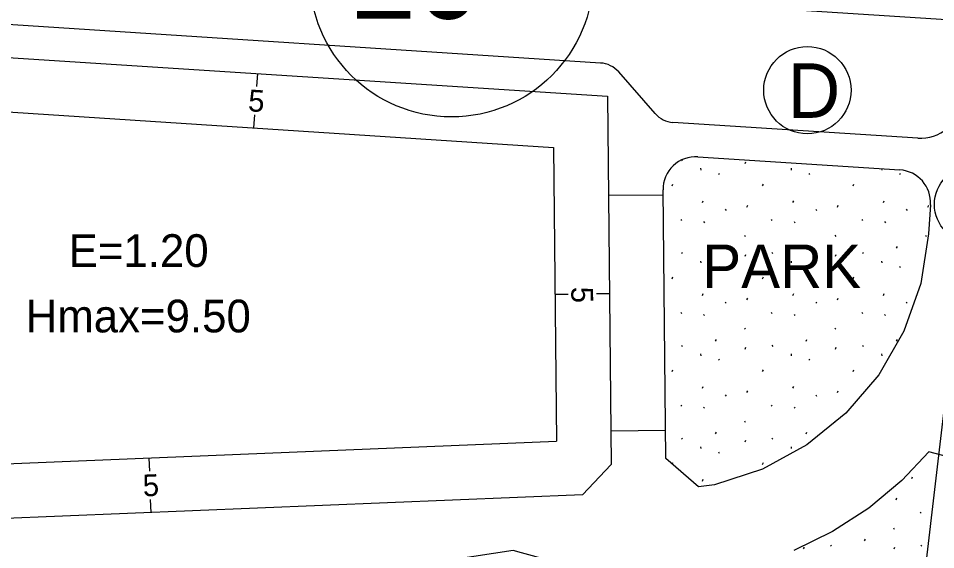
# Model space of a CAD drawing. Extents: x 419396 to 421519, y 4453567 to 4456767.
# Drawn here: x 421028 to 421112.1, y 4454579.1 to 4454627.8 of the extents above; entities that cross this region are included whole.
import ezdxf

# ---------------------------------------------------------------- set-up
doc = ezdxf.new("R2010")
doc.units = 0
for name, color, linetype in [('0_KADASTRO', 7, 'Continuous'), ('Level 20', 7, 'Continuous'), ('Level 28', 7, 'Continuous'), ('Level 29', 7, 'Continuous'), ('Level 30', 7, 'Continuous'), ('Level 41', 7, 'Continuous'), ('Level 55', 7, 'Continuous'), ('Level 58', 7, 'Continuous'), ('Level 61', 7, 'Continuous'), ('Level 62', 7, 'Continuous')]:
    doc.layers.add(name, color=color, linetype=linetype)

msp = doc.modelspace()

# ---------------------------------------------------------------- linework, layer by layer
at = {"layer": '0_KADASTRO'}
msp.add_lwpolyline([(421115.84, 4454617.61), (421110.18, 4454569.28), (421098.82, 4454573.19), (421092.11, 4454575.5), (421080.7, 4454577), (421079.93, 4454577.22), (421074.145, 4454578.816), (421073.377, 4454579.023), (421024.86, 4454571.61), (421009.61, 4454569.68), (420998.5, 4454570.68), (420995.77, 4454570.92), (420986.29, 4454574.29), (420978.09, 4454579.98), (420972.54, 4454590.07), (420970.25, 4454598.21), (420978.09, 4454629.67)], dxfattribs=at)
at = {"layer": 'Level 20'}
for p, q in [((421049.935, 4454622.751), (421049.857, 4454621.553)), ((421022.161, 4454619.544), (421077.061, 4454615.978)), ((421049.611, 4454617.761), (421049.689, 4454618.959)), ((421077.061, 4454615.978), (421077.335, 4454589.037)), ((421077.198, 4454602.507), (421078.398, 4454602.52)), ((421082.198, 4454602.558), (421080.998, 4454602.546)), ((421002.656, 4454585.956), (421077.335, 4454589.037)), ((421039.996, 4454587.496), (421040.045, 4454586.297)), ((421040.202, 4454582.501), (421040.152, 4454583.7))]:
    msp.add_line(p, q, dxfattribs=at)
at = {"layer": 'Level 28'}
for p, q in [((421082.012, 4454620.666), (421082.357, 4454586.895)), ((421090.294, 4454615.118), (421108.803, 4454613.915)), ((421087.105, 4454611.613), (421082.105, 4454611.562)), ((421087.351, 4454587.453), (421087.1, 4454612.093)), ((421111.602, 4454610.727), (421111.429, 4454608.062)), ((421111.429, 4454608.062), (421110.709, 4454603.496)), ((421110.709, 4454603.496), (421109.17, 4454599.138)), ((421109.17, 4454599.138), (421106.862, 4454595.132)), ((421106.862, 4454595.132), (421103.865, 4454591.614)), ((421103.865, 4454591.614), (421100.277, 4454588.7)), ((421087.325, 4454590.016), (421082.326, 4454589.965)), ((421100.277, 4454588.7), (421096.218, 4454586.488)), ((421111.47, 4454588.069), (421108.986, 4454585.442)), ((421114.544, 4454587.245), (421111.47, 4454588.069)), ((421090.35, 4454584.856), (421087.351, 4454587.453)), ((421082.357, 4454586.895), (421079.731, 4454584.131)), ((421096.218, 4454586.488), (421091.824, 4454585.053)), ((421108.986, 4454585.442), (421105.95, 4454582.913)), ((421091.824, 4454585.053), (421090.35, 4454584.856)), ((421105.95, 4454582.913), (421102.636, 4454580.76)), ((421102.636, 4454580.76), (421099.09, 4454579.016))]:
    msp.add_line(p, q, dxfattribs=at)
for centre, start, end in [((421090.1, 4454612.124), 86.2833, 180.58463), ((421108.608, 4454610.922), 356.2833, 86.2833)]:
    msp.add_arc(centre, 3, start, end, dxfattribs=at)
at = {"layer": 'Level 29'}
for p, q in [((421021.843, 4454624.575), (421082.012, 4454620.666)), ((421079.731, 4454584.131), (421001.95, 4454580.922))]:
    msp.add_line(p, q, dxfattribs=at)
at = {"layer": 'Level 41'}
for p, q in [((421088.811, 4454614.816), (421088.857, 4454614.747)), ((421094.614, 4454614.509), (421094.686, 4454614.669)), ((421090.544, 4454614.063), (421090.562, 4454613.903)), ((421098.837, 4454614.063), (421098.855, 4454613.903)), ((421107.134, 4454614.024), (421107.148, 4454613.903)), ((421092.174, 4454613.593), (421092.244, 4454613.486)), ((421100.467, 4454613.593), (421100.537, 4454613.486)), ((421108.76, 4454613.593), (421108.83, 4454613.486)), ((421087.937, 4454612.449), (421088.009, 4454612.609)), ((421096.23, 4454612.449), (421096.302, 4454612.609)), ((421104.523, 4454612.449), (421104.595, 4454612.609)), ((421090.709, 4454610.919), (421090.779, 4454611.079)), ((421094.792, 4454610.511), (421094.863, 4454610.671)), ((421099.002, 4454610.919), (421099.072, 4454611.079)), ((421103.085, 4454610.511), (421103.156, 4454610.671)), ((421107.295, 4454610.919), (421107.365, 4454611.079)), ((421111.378, 4454610.511), (421111.449, 4454610.671)), ((421092.804, 4454610.303), (421092.875, 4454610.197)), ((421101.097, 4454610.303), (421101.168, 4454610.197)), ((421109.39, 4454610.303), (421109.461, 4454610.197)), ((421088.719, 4454609.374), (421088.79, 4454609.267)), ((421090.818, 4454609.182), (421090.889, 4454609.075)), ((421097.012, 4454609.374), (421097.083, 4454609.267)), ((421099.111, 4454609.182), (421099.182, 4454609.075)), ((421105.305, 4454609.374), (421105.376, 4454609.267)), ((421107.404, 4454609.182), (421107.475, 4454609.075)), ((421094.556, 4454607.921), (421094.627, 4454607.814)), ((421102.849, 4454607.921), (421102.92, 4454607.814)), ((421111.142, 4454607.921), (421111.213, 4454607.814)), ((421088.786, 4454606.344), (421088.857, 4454606.237)), ((421091.915, 4454606.728), (421091.986, 4454606.887)), ((421097.079, 4454606.344), (421097.15, 4454606.237)), ((421100.208, 4454606.728), (421100.279, 4454606.887)), ((421105.372, 4454606.344), (421105.443, 4454606.237)), ((421108.501, 4454606.728), (421108.572, 4454606.887)), ((421090.544, 4454605.553), (421090.562, 4454605.393)), ((421094.614, 4454605.999), (421094.686, 4454606.159)), ((421098.837, 4454605.553), (421098.855, 4454605.393)), ((421102.907, 4454605.999), (421102.979, 4454606.159)), ((421107.13, 4454605.553), (421107.148, 4454605.393)), ((421092.174, 4454605.083), (421092.244, 4454604.976)), ((421100.467, 4454605.083), (421100.537, 4454604.976)), ((421108.76, 4454605.083), (421108.83, 4454604.976)), ((421087.937, 4454603.939), (421088.009, 4454604.099)), ((421096.23, 4454603.939), (421096.302, 4454604.099)), ((421104.523, 4454603.939), (421104.595, 4454604.099)), ((421090.709, 4454602.409), (421090.779, 4454602.569)), ((421094.792, 4454602.001), (421094.863, 4454602.161)), ((421099.002, 4454602.409), (421099.072, 4454602.569)), ((421103.085, 4454602.001), (421103.156, 4454602.161)), ((421107.295, 4454602.409), (421107.365, 4454602.569)), ((421092.804, 4454601.793), (421092.875, 4454601.687)), ((421101.097, 4454601.793), (421101.168, 4454601.687)), ((421109.39, 4454601.793), (421109.461, 4454601.687)), ((421088.719, 4454600.864), (421088.79, 4454600.757)), ((421090.818, 4454600.672), (421090.889, 4454600.565)), ((421097.012, 4454600.864), (421097.083, 4454600.757)), ((421099.111, 4454600.672), (421099.182, 4454600.565)), ((421105.305, 4454600.864), (421105.376, 4454600.757)), ((421107.404, 4454600.672), (421107.475, 4454600.565)), ((421094.556, 4454599.411), (421094.627, 4454599.304)), ((421102.849, 4454599.411), (421102.92, 4454599.304)), ((421091.915, 4454598.218), (421091.986, 4454598.377)), ((421100.208, 4454598.218), (421100.279, 4454598.377)), ((421108.501, 4454598.218), (421108.572, 4454598.377)), ((421088.786, 4454597.834), (421088.857, 4454597.727)), ((421090.544, 4454597.043), (421090.562, 4454596.883)), ((421094.614, 4454597.489), (421094.686, 4454597.649)), ((421097.079, 4454597.834), (421097.15, 4454597.727)), ((421098.837, 4454597.043), (421098.855, 4454596.883)), ((421102.907, 4454597.489), (421102.979, 4454597.649)), ((421105.372, 4454597.834), (421105.443, 4454597.727)), ((421107.13, 4454597.043), (421107.148, 4454596.883)), ((421092.174, 4454596.573), (421092.244, 4454596.466)), ((421100.467, 4454596.573), (421100.537, 4454596.466)), ((421087.937, 4454595.429), (421088.009, 4454595.589)), ((421096.23, 4454595.429), (421096.302, 4454595.589)), ((421104.523, 4454595.429), (421104.595, 4454595.589)), ((421090.709, 4454593.899), (421090.779, 4454594.059)), ((421094.792, 4454593.491), (421094.863, 4454593.651)), ((421099.002, 4454593.899), (421099.072, 4454594.059)), ((421103.085, 4454593.491), (421103.156, 4454593.651)), ((421092.804, 4454593.283), (421092.875, 4454593.177)), ((421101.097, 4454593.283), (421101.168, 4454593.177)), ((421088.719, 4454592.354), (421088.79, 4454592.247)), ((421090.818, 4454592.162), (421090.889, 4454592.055)), ((421097.012, 4454592.354), (421097.083, 4454592.247)), ((421099.111, 4454592.162), (421099.182, 4454592.055)), ((421094.556, 4454590.901), (421094.627, 4454590.794)), ((421102.849, 4454590.901), (421102.897, 4454590.828)), ((421091.915, 4454589.708), (421091.986, 4454589.867)), ((421100.208, 4454589.708), (421100.279, 4454589.867)), ((421088.786, 4454589.324), (421088.857, 4454589.217)), ((421094.614, 4454588.979), (421094.686, 4454589.139)), ((421097.079, 4454589.324), (421097.15, 4454589.217)), ((421090.544, 4454588.533), (421090.562, 4454588.373)), ((421092.174, 4454588.063), (421092.244, 4454587.956)), ((421098.837, 4454588.533), (421098.855, 4454588.373)), ((421087.946, 4454586.939), (421088.009, 4454587.079)), ((421096.23, 4454586.919), (421096.302, 4454587.079)), ((421090.709, 4454585.389), (421090.779, 4454585.549)), ((421109.886, 4454585.617), (421109.958, 4454585.777)), ((421108.448, 4454583.679), (421108.519, 4454583.839)), ((421106.517, 4454583.385), (421106.531, 4454583.365)), ((421110.668, 4454582.542), (421110.739, 4454582.435)), ((421108.212, 4454581.089), (421108.283, 4454580.982)), ((421102.442, 4454579.512), (421102.513, 4454579.405)), ((421105.571, 4454579.896), (421105.642, 4454580.055)), ((421110.735, 4454579.512), (421110.806, 4454579.405)), ((421099.977, 4454579.167), (421100.049, 4454579.327)), ((421108.27, 4454579.167), (421108.342, 4454579.327))]:
    msp.add_line(p, q, dxfattribs=at)
at = {"layer": 'Level 55'}
msp.add_circle((421115.469, 4454610.755), 3.5, dxfattribs=at)
at = {"layer": 'Level 58'}
msp.add_circle((421067.721, 4454631.775), 13, dxfattribs=at)
at = {"layer": 'Level 61'}
msp.add_circle((421100.329, 4454621.226), 4, dxfattribs=at)
at = {"layer": 'Level 62'}
for p, q in [((421262.433, 4454617.968), (421020.267, 4454633.699)), ((421081.364, 4454623.718), (421019.949, 4454627.707)), ((421086.389, 4454619.075), (421083.037, 4454622.894)), ((421110.445, 4454616.818), (421088.015, 4454618.275))]:
    msp.add_line(p, q, dxfattribs=at)
for centre, radius, start, end in [((421081.206, 4454621.286), 2.437, 41.2833, 86.2833), ((421088.168, 4454620.637), 2.367, 221.2833, 266.2833), ((421110.687, 4454620.551), 3.741, 266.2833, 311.2833)]:
    msp.add_arc(centre, radius, start, end, dxfattribs=at)

# ---------------------------------------------------------------- texts
at = {"layer": 'Level 20'}
for rotation, p in [(356.28329, (421049.043, 4454619.301)), (270.58464, (421078.691, 4454603.189)), (2.36252, (421039.474, 4454583.972))]:
    msp.add_text('5', height=2, rotation=rotation, dxfattribs=at).set_placement(p)
at = {"layer": 'Level 30'}
for s, p in [('E=1.20', (421032.643, 4454605.018)), ('Hmax=9.50', (421028.706, 4454599.018))]:
    msp.add_text(s, height=3, dxfattribs=at).set_placement(p)
at = {"layer": 'Level 58'}
msp.add_text('20', height=7.9934, dxfattribs=at).set_placement((421058.528, 4454627.779))
at = {"layer": 'Level 61'}
for s, height, p in [('D', 5, (421098.518, 4454618.69)), ('PARK', 4, (421090.693, 4454603.075))]:
    msp.add_text(s, height=height, dxfattribs=at).set_placement(p)

doc.saveas('drawing.dxf')
